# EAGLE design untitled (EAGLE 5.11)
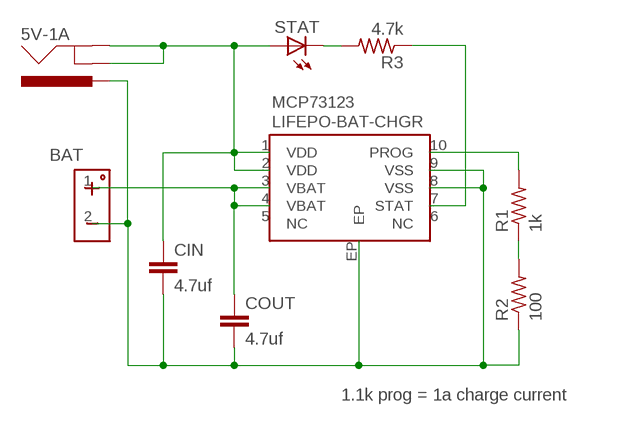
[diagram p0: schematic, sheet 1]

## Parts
5V-1A  POWER_JACKSLT  [POWER_JACK_SLOT]
BAT  HEADER-POWER  [HEADER-POWER]
CIN  4.7uf  C-EUC0805  [C0805]
COUT  4.7uf  C-EUC0805  [C0805]
LIFEPO-BAT-CHGR  MCP73123  [10-DFN-EP]
R1  1k  R-US_R1210  [R1210]
R2  100  R-US_R1210  [R1210]
R3  4.7k  R-US_R1210  [R1210]
STAT  LEDCHIP-LED0805  [CHIP-LED0805]

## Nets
GND: 5V-1A.PWR BAT.2 CIN.2 COUT.2 LIFEPO-BAT-CHGR.8(VSS) LIFEPO-BAT-CHGR.9(VSS) LIFEPO-BAT-CHGR.EP R2.1
N$1: R1.1 R2.2
N$2: LIFEPO-BAT-CHGR.10(PROG) R1.2
N$4: R3.2 STAT.C
N$6: BAT.1 COUT.1 LIFEPO-BAT-CHGR.3(VBAT) LIFEPO-BAT-CHGR.4(VBAT)
N$7: LIFEPO-BAT-CHGR.7(STAT) R3.1
VIN: 5V-1A.GND@1(GNDBREAK) 5V-1A.GND@2(GND) CIN.1 LIFEPO-BAT-CHGR.1(VDD) LIFEPO-BAT-CHGR.2(VDD) STAT.A
Unconnected: LIFEPO-BAT-CHGR.5(NC) LIFEPO-BAT-CHGR.6(NC)

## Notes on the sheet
- 1.1k prog = 1a charge current

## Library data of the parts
5V-1A = SparkFun2011-02-20:POWER_JACK: Power Jack This is the standard 5.5mm barrel jack for power. The PTH is the most common, proven, reliable, footprint. All others are experimental. The Slot footprint only works if the mill layer is transmitted to the PCB fab house so be warned. Spark Fun Electronics SKU : PRT-00119. Mating wall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
BAT = trl:HEADER-POWER
CIN COUT = rcl:C-EU: CAPACITOR, European symbol
LIFEPO-BAT-CHGR = trl:MCP73123
R1-R3 = resistor:R-US_: RESISTOR, American symbol
STAT = led:LED: LED

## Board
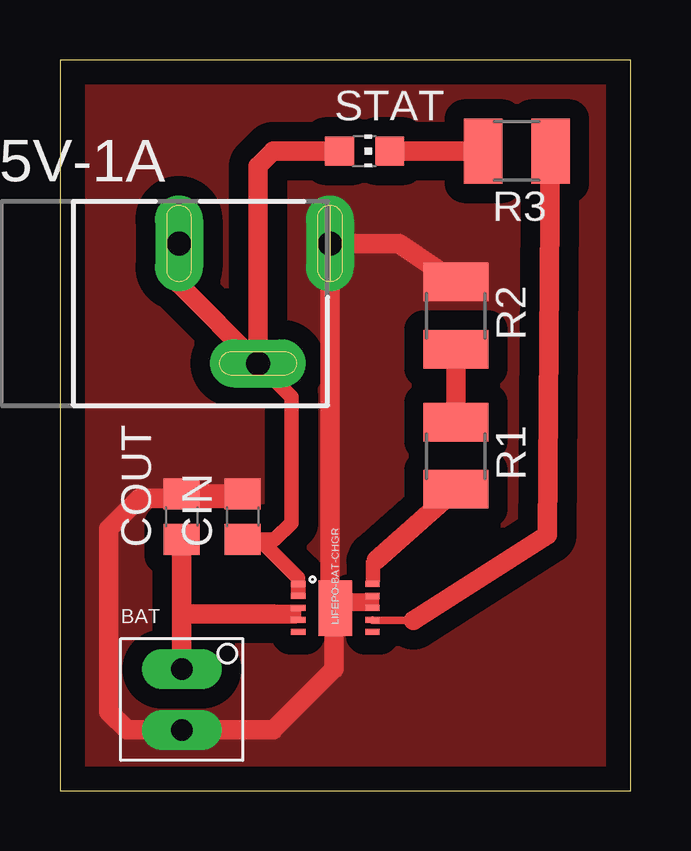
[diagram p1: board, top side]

Size 23.8 x 30.47 mm. Coordinates in mm from the lower left corner, seen from the top.
Outline: 0,0 23.8,0 23.8,30.47 0,30.47 0,0
Copper layers (1*16): Top 0.035mm / dielectric 1.5mm / Bottom 0.035mm
Design rules "default": minimum track width 10mil, minimum drill 0.6mm, track to track 8mil, track to pad 8mil, pad to pad 8mil, via to via 8mil, smd to smd 8mil, copper to edge 40mil, drill to drill 8mil, minimum pad ring 10mil, minimum via ring 8mil, stop-mask expansion 4mil, vias tented up to drill 0mil, thermal gap 10mil

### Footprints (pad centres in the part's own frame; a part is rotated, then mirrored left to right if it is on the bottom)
POWER_JACK_SLOT = drill 1 pad 2 long: GND@1 2.58,7.5; GND@2 7.58,10.8; PWR 2.58,13.8
HEADER-POWER = drill 0.9 pad 1.676 long: 1 0,1.27; 2 0,-1.27
C0805 = smd 1.3 x 1.5: 1 -0.95,0; 2 0.95,0
10-DFN-EP = smd 0.6 x 0.25: 1 -1.5,1; 2 -1.5,0.5; 3 -1.5,0; 4 -1.5,-0.5; 5 -1.5,-1; 6 1.6,-1; 7 1.6,-0.5; 8 1.6,0; 9 1.6,0.5; 10 1.6,1 | smd 1.4 x 2.3: EP 0.05,0
R1210 = smd 1.6 x 2.7: 1 -1.4,0; 2 1.4,0
CHIP-LED0805 = smd 1.2 x 1.2: A 0,-1.05; C 0,1.05

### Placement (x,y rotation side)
5V-1A  -2.54,25.4 270 top
BAT  5.08,3.81 0 top
CIN  7.62,11.43 90 top
COUT  5.08,11.43 90 top
LIFEPO-BAT-CHGR  11.43,7.62 0 top
R1  16.51,13.97 270 top
R2  16.51,19.81 270 top
R3  19.05,26.67 180 top
STAT  12.7,26.67 270 top

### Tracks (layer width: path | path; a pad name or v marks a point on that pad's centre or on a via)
GND
  Top 0.254: LIFEPO-BAT-CHGR.EP LIFEPO-BAT-CHGR.8 LIFEPO-BAT-CHGR.9
  Top 0.305: 7.81,12.19 CIN.2 | LIFEPO-BAT-CHGR.EP 11.26,7.84
  Top 0.813: R2.1 14.14,22.82 5V-1A.PWR 11.26,7.84 | CIN.2 COUT.2 | LIFEPO-BAT-CHGR.EP 11.43,7.57 11.43,5.08 8.89,2.54 BAT.2 2.79,2.54 2.03,3.3 2.03,10.92 3.3,12.19 7.81,12.19
  pour Top (isolate 0.813, no thermals): 0,0 23.8,0 23.8,30.45 0.05,30.45 0.05,30.23 0,30.23
N$1
  Top 0.813: R1.1 R2.2
N$2
  Top 0.254: LIFEPO-BAT-CHGR.10 13.03,9.46 13.21,9.64
  Top 0.813: 13.21,9.64 R1.2
N$4
  Top 0.813: STAT.C R3.2
N$6
  Top 0.254: LIFEPO-BAT-CHGR.4 LIFEPO-BAT-CHGR.3 9.91,7.62 9.65,7.37 8.89,7.37
  Top 0.813: 8.89,7.37 5.33,7.37 5.08,7.62 | 5.08,7.62 COUT.1 | BAT.1 5.08,7.62
N$7
  Top 0.305: 14.73,7.11 LIFEPO-BAT-CHGR.7
  Top 0.813: R3.1 20.32,10.67 14.73,7.11
VIN
  Top 0.254: LIFEPO-BAT-CHGR.2 LIFEPO-BAT-CHGR.1
  Top 0.61: LIFEPO-BAT-CHGR.1 9.93,8.87 8.38,10.41 7.69,10.41 CIN.1 8.96,10.48 9.65,11.18 9.65,16.43 5V-1A.GND@2
  Top 0.813: 5V-1A.GND@1 4.96,21.12 5V-1A.GND@2 8.26,26.04 8.89,26.67 STAT.A
(copper drawn outside any net)
  shapes: Top area x4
